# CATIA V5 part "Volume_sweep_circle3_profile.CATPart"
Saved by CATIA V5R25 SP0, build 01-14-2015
Part number: Part1
Bounding box of the stored display mesh (mm): x -210.021 to 26.553, y 0 to 145.736, z -55 to 54.999
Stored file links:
  E:\cadcim\GSD_cat_v5-6r2014\Part_files\Volume_sweep_circle3_profile.CATPart
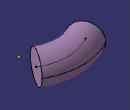
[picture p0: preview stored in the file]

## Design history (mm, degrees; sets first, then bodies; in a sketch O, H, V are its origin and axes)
Set1
  Sketch1 on xy-plane, origin (0, 0, 0), H (1, 0, 0), V (0, 1, 0)
    line L1 (0, 0) -> (-183.1008, 0)
    horizontal: L1 H
  Sketch2 on xy-plane, origin (0, 0, 0), H (1, 0, 0), V (0, 1, 0)
    spline S1 through (0, 65.5148) (-89.6654, 90.7245) (-183.6013, 65.5148)
    point P1 (0, 65.5148)
    coincidence: P1 V
  Sweep1: type Circle, Guide Sketch2, Radius 55
Body1 (main body)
